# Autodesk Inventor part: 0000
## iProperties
Shininess: 64.0
Length Units: 11269
Angle Units: 11279
Time Units: 11290
Mass Units: 11283
Length Display Precision: 3
Angle Display Precision: 2
Compacted: True
Part Number: 0000
Document SubType Name: Modeling
Created: 2004-02
Material: Par défaut
Project: GB000
Manufacturer: Standard
Standards Organization: Custom
Density: 0.0
Volumn: 0.0
Area: 0.0
PropertySet Name: Model Information
Control State: 0
Master: False
Checked Out: False
Observations: -
Revision Number: 00
